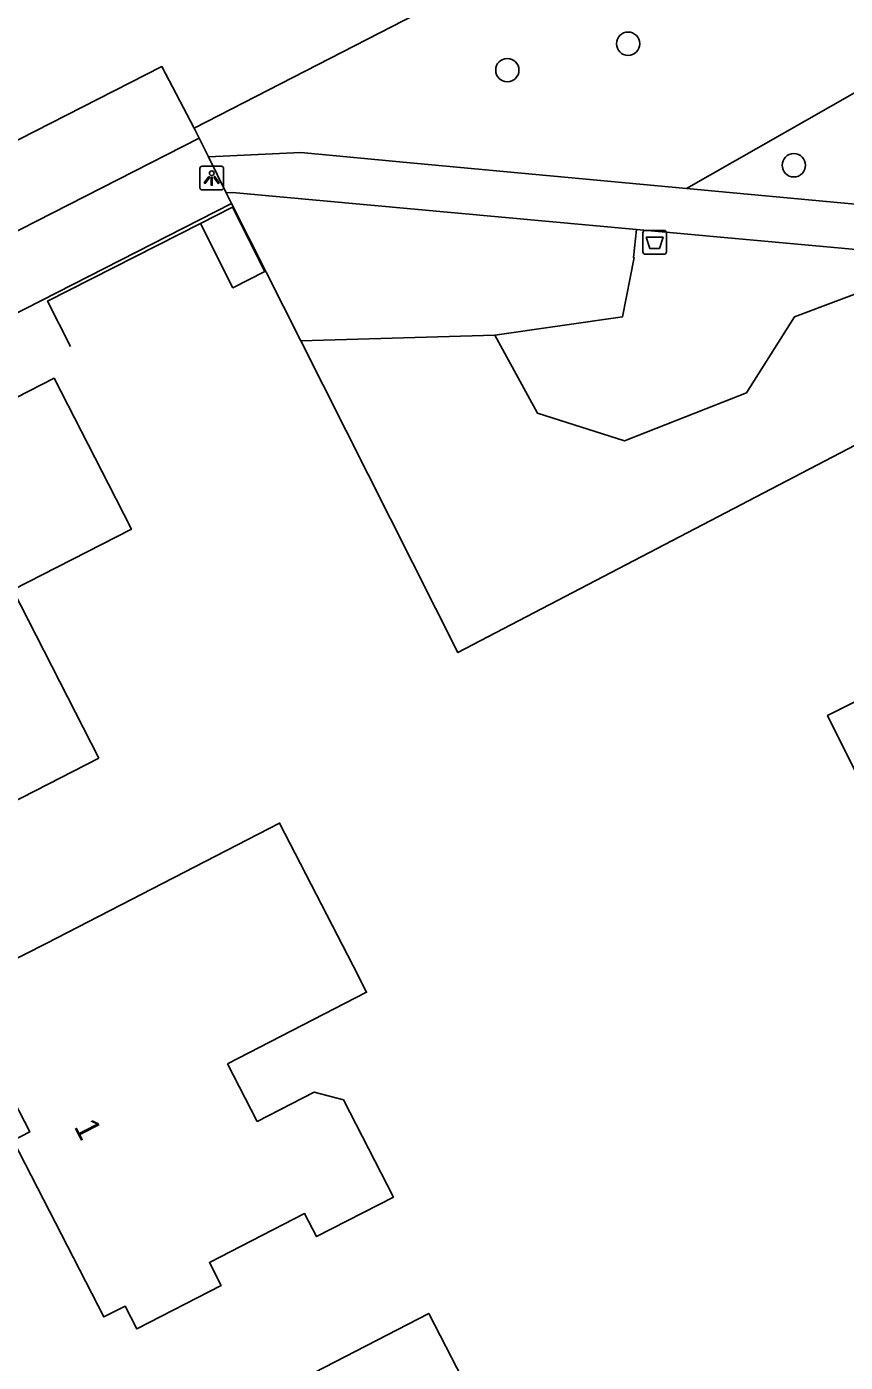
# Model space of a CAD drawing. Extents: x 162722 to 165099, y 384721 to 386283.
# Drawn here: x 163696 to 163730.3, y 384983.4 to 385039.4 of the extents above; entities that cross this region are included whole.
import ezdxf

# ---------------------------------------------------------------- set-up
doc = ezdxf.new("R2010")
doc.units = 0
for name, color, linetype in [('IMGEO_Afvalbak', 7, 'Continuous'), ('IMGEO_Boom', 7, 'Continuous'), ('IMGEO_Groenvoorziening', 7, 'Continuous'), ('IMGEO_Lichtpunt', 7, 'Continuous'), ('IMGEO_Muur', 7, 'Continuous'), ('IMGEO_Pand', 7, 'Continuous'), ('IMGEO_Pand_nummerreeks', 7, 'Continuous'), ('IMGEO_Voetpad_open', 7, 'Continuous')]:
    doc.layers.add(name, color=color, linetype=linetype)

msp = doc.modelspace()

# ---------------------------------------------------------------- linework, layer by layer
at = {"layer": 'IMGEO_Afvalbak'}
for p, q in [((163721.847, 385029.95), (163721.847, 385030.75)), ((163721.847, 385030.75), (163721.847, 385029.95)), ((163721.947, 385030.85), (163722.737, 385030.85)), ((163722.737, 385030.85), (163721.947, 385030.85)), ((163722.837, 385030.75), (163722.837, 385029.95)), ((163722.837, 385029.95), (163722.837, 385030.75)), ((163722.737, 385029.85), (163721.947, 385029.85)), ((163721.947, 385029.85), (163722.737, 385029.85))]:
    msp.add_line(p, q, dxfattribs=at)
msp.add_lwpolyline([(163721.99, 385030.564), (163722.694, 385030.564), (163722.545, 385030.094), (163722.139, 385030.094), (163721.99, 385030.564)], dxfattribs=at)
for centre, start, end in [((163721.947, 385030.75), 90, 180), ((163721.947, 385030.75), 90, 180), ((163722.737, 385030.75), 0, 90), ((163722.737, 385030.75), 360, 90), ((163721.947, 385029.95), 180, 270), ((163721.947, 385029.95), 180, 270), ((163722.737, 385029.95), 270, 0), ((163722.737, 385029.95), 270, 0)]:
    msp.add_arc(centre, 0.1, start, end, dxfattribs=at)
at = {"layer": 'IMGEO_Boom'}
for centre in [(163721.229, 385038.685), (163716.159, 385037.575), (163728.184, 385033.584)]:
    msp.add_circle(centre, 0.489, dxfattribs=at)
at = {"layer": 'IMGEO_Groenvoorziening'}
for points in [[(163712.333, 385039.928), (163703.015, 385035.139)], [(163733.752, 385038.348), (163723.683, 385032.609)], [(163672.955, 385023.086), (163701.659, 385037.727), (163703.015, 385035.139)], [(163703.015, 385035.139), (163703.221, 385034.728)], [(163707.49, 385026.219), (163704.586, 385031.975)], [(163721.576, 385030.897), (163721.45, 385029.722), (163721.476, 385029.719), (163720.994, 385027.228), (163715.637, 385026.452)], [(163715.637, 385026.452), (163717.423, 385023.192), (163721.071, 385022.027), (163726.195, 385024.046), (163728.214, 385027.228), (163731.94, 385028.626), (163733.096, 385029.842)], [(163738.567, 385026.557), (163738.822, 385026.058), (163738.155, 385025.71), (163714.087, 385013.147), (163707.49, 385026.219)], [(163715.637, 385026.452), (163707.49, 385026.219)]]:
    msp.add_lwpolyline(points, dxfattribs=at)
at = {"layer": 'IMGEO_Lichtpunt'}
for p, q in [((163703.254, 385033.451), (163703.254, 385032.644)), ((163703.254, 385033.451), (163703.254, 385032.644)), ((163704.156, 385033.546), (163703.348, 385033.546)), ((163704.156, 385033.546), (163703.348, 385033.546)), ((163704.25, 385032.644), (163704.25, 385033.451)), ((163704.25, 385032.644), (163704.25, 385033.451)), ((163703.348, 385032.55), (163704.156, 385032.55)), ((163703.348, 385032.55), (163704.156, 385032.55))]:
    msp.add_line(p, q, dxfattribs=at)
for points in [[(163703.628, 385033.115), (163703.667, 385033.087), (163703.479, 385032.825), (163703.441, 385032.852), (163703.628, 385033.115)], [(163703.73, 385033.067), (163703.777, 385033.067), (163703.777, 385032.745), (163703.73, 385032.745), (163703.73, 385033.067)], [(163703.84, 385033.087), (163703.878, 385033.114), (163704.065, 385032.852), (163704.026, 385032.824), (163703.84, 385033.087)]]:
    msp.add_lwpolyline(points, dxfattribs=at)
msp.add_circle((163703.753, 385033.249), 0.0994, dxfattribs=at)
for centre, start, end in [((163703.348, 385033.451), 90, 180), ((163703.348, 385033.451), 90, 180), ((163704.156, 385033.451), 0, 90), ((163704.156, 385033.451), 0, 90), ((163703.348, 385032.644), 180, 270), ((163703.348, 385032.644), 180, 270), ((163704.156, 385032.644), 270, 0), ((163704.156, 385032.644), 270, 360)]:
    msp.add_arc(centre, 0.0946, start, end, dxfattribs=at)
at = {"layer": 'IMGEO_Muur'}
msp.add_lwpolyline([(163703.275, 385031.14), (163696.86, 385027.888), (163697.828, 385025.98)], dxfattribs=at)
at = {"layer": 'IMGEO_Pand'}
for points in [[(163703.275, 385031.14), (163704.62, 385031.822), (163705.986, 385029.128), (163704.64, 385028.446), (163703.275, 385031.14)], [(163699.013, 385008.722), (163694.173, 385006.241), (163689.723, 385003.96), (163682.864, 385017.343), (163697.134, 385024.658), (163699.414, 385020.209), (163700.379, 385018.327), (163695.398, 385015.774), (163699.013, 385008.722)], [(163741.316, 385009.636), (163740.111, 385012.059), (163739.801, 385012.683), (163739.025, 385014.244), (163741.647, 385015.547), (163739.47, 385019.924), (163735.204, 385017.803), (163731.149, 385015.787), (163732.948, 385012.168), (163729.604, 385010.506), (163732.271, 385005.142)], [(163704.42, 384995.895), (163705.664, 384993.477), (163708.058, 384994.708), (163709.28, 384994.388), (163711.379, 384990.308), (163708.151, 384988.647), (163707.652, 384989.614), (163703.656, 384987.558), (163704.151, 384986.598), (163700.612, 384984.777), (163700.117, 384985.737), (163699.227, 384985.279), (163695.418, 384992.682), (163696.113, 384993.039), (163695.202, 384994.809), (163694.508, 384994.452), (163692.344, 384998.657), (163694.955, 385000), (163696.797, 385000.947), (163706.599, 385005.991), (163709.682, 385000), (163710.25, 384998.894), (163704.42, 384995.895)], [(163717.064, 384970.82), (163712.943, 384968.69), (163713.412, 384967.784), (163710.036, 384966.039), (163709.567, 384966.945), (163708.838, 384966.568), (163703.306, 384977.267), (163706.282, 384978.806), (163704.968, 384981.348), (163712.859, 384985.428), (163714.756, 384981.76), (163715.26, 384982.021), (163717.987, 384976.746), (163714.841, 384975.12), (163717.064, 384970.82)]]:
    msp.add_lwpolyline(points, dxfattribs=at)
at = {"layer": 'IMGEO_Voetpad_open'}
for points in [[(163674.583, 385020.123), (163703.221, 385034.728)], [(163703.221, 385034.728), (163703.613, 385033.936)], [(163703.613, 385033.936), (163707.487, 385034.117), (163712.242, 385033.674), (163723.683, 385032.609)], [(163703.613, 385033.936), (163704.363, 385032.424)], [(163721.576, 385030.897), (163704.628, 385032.449), (163704.363, 385032.424)], [(163704.363, 385032.424), (163704.586, 385031.975)], [(163723.683, 385032.609), (163733.478, 385031.697)], [(163704.586, 385031.975), (163675.935, 385017.371)], [(163733.096, 385029.842), (163721.576, 385030.897)]]:
    msp.add_lwpolyline(points, dxfattribs=at)

# ---------------------------------------------------------------- texts
at = {"layer": 'IMGEO_Pand_nummerreeks'}
msp.add_text('1', height=1, rotation=297.2259, dxfattribs=at).set_placement((163697.952, 384993.264))

doc.saveas('drawing.dxf')
